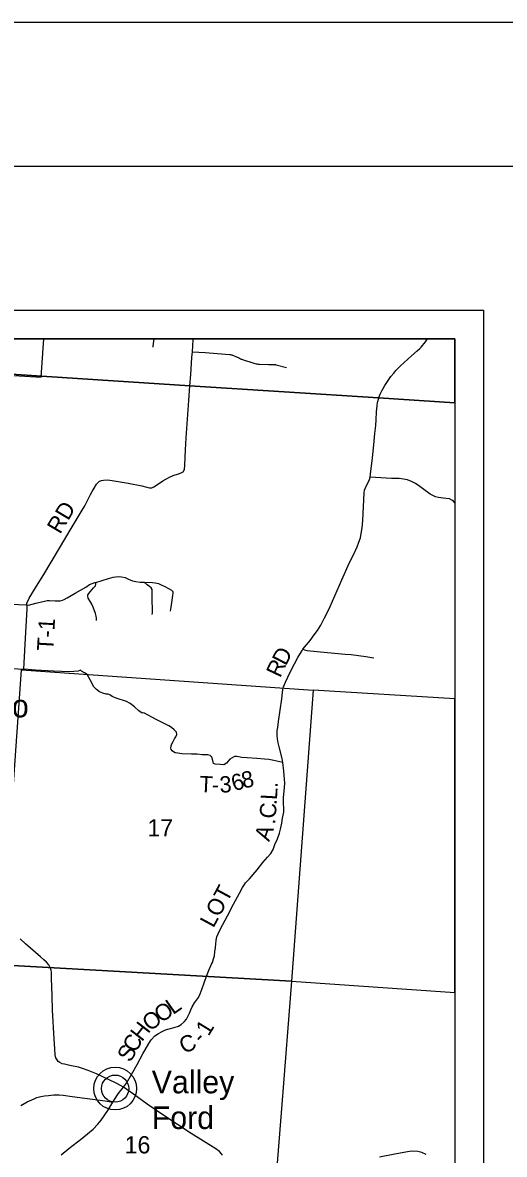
# Model space of a CAD drawing. Extents: x 0 to 34, y 0 to 22.
# Drawn here: x 7.394 to 9.072, y 18.062 to 22 of the extents above; entities that cross this region are included whole.
import ezdxf

# ---------------------------------------------------------------- set-up
doc = ezdxf.new("R2010")
doc.units = 0
for name, color, linetype in [('GM_X_Corporation', 7, 'Continuous'), ('GM_X_County_Road', 7, 'Continuous'), ('GM_X_County_Road_Text', 7, 'Continuous'), ('GM_X_Section_Text', 7, 'Continuous'), ('GM_X_State_Route', 7, 'Continuous'), ('GM_X_Township_Road', 7, 'Continuous'), ('GM_X_Township_Road_Text', 7, 'Continuous'), ('GM_X_Township_Text', 7, 'Continuous'), ('GM_X_Unincorporated', 7, 'Continuous'), ('GM_X_Unincorporated_Location', 7, 'Continuous'), ('GM_X_Unincorporated_Text', 7, 'Continuous'), ('SH_Border', 7, 'Continuous'), ('SH_Cut_Line', 7, 'Continuous'), ('SH_Data', 7, 'Continuous')]:
    doc.layers.add(name, color=color, linetype=linetype)

msp = doc.modelspace()

# ---------------------------------------------------------------- linework, layer by layer
at = {"layer": 'GM_X_Corporation'}
for points in [[(8.9, 20.6767), (8.9, 20.9), (6.4339, 20.9), (6.4275, 20.8307), (6.8677, 20.8085), (6.8847, 20.8074), (7.2108, 20.7862), (7.9767, 20.7364), (8.6343, 20.694)], [(8.9, 20.6767), (8.9, 20.9), (6.4339, 20.9), (6.4275, 20.8307), (6.8677, 20.8085), (6.8847, 20.8074), (7.2108, 20.7862), (7.9767, 20.7364), (8.6343, 20.694)], [(7.4684, 20.9), (6.4334, 20.9), (6.4281, 20.8286), (7.4587, 20.7663)], [(7.3904, 19.7475), (8.4063, 19.6773), (8.3303, 18.6644), (7.3179, 18.7214)], [(8.9, 18.6256), (8.9, 19.6469), (8.4063, 19.6773), (8.3303, 18.6644)], [(7.3179, 18.7214), (8.3303, 18.6644), (8.2967, 18.2357), (8.2648, 17.8281), (8.2474, 17.6405), (7.6907, 17.673), (7.2488, 17.7032), (7.2611, 17.894), (7.2923, 18.3534)]]:
    msp.add_lwpolyline(points, close=True, dxfattribs=at)
at = {"layer": 'GM_X_County_Road'}
for points in [[(8.6345, 20.6935), (8.6374, 20.7012), (8.64, 20.707), (8.6453, 20.7182), (8.6496, 20.7264), (8.6557, 20.7372), (8.6623, 20.7477), (8.6696, 20.7584), (8.677, 20.7684), (8.6867, 20.7805), (8.6943, 20.7894), (8.6969, 20.7924), (8.6998, 20.7953), (8.71, 20.8053), (8.7483, 20.8406), (8.7685, 20.8581), (8.7776, 20.8665), (8.7819, 20.8709), (8.787, 20.8764), (8.793, 20.8836), (8.7976, 20.8895), (8.8049, 20.9)], [(7.746, 18.2957), (7.756, 18.3098), (7.7736, 18.3395), (7.7936, 18.3746), (7.8133, 18.4121), (7.8333, 18.4476), (7.8417, 18.4609), (7.855, 18.4742), (7.867, 18.4828), (7.8798, 18.4898), (7.8922, 18.4947), (7.9052, 18.499), (7.922, 18.5034), (7.9367, 18.508), (7.9461, 18.5134), (7.957, 18.5227), (7.965, 18.5326), (7.9699, 18.5412), (7.9757, 18.5531), (7.9801, 18.5648), (7.9851, 18.5755), (7.9928, 18.5893), (8.0072, 18.608), (8.0131, 18.6201), (8.0196, 18.6393), (8.0254, 18.6549), (8.0341, 18.6824), (8.0436, 18.7053), (8.0525, 18.7235), (8.0551, 18.7301), (8.0595, 18.7424), (8.0623, 18.7527), (8.0642, 18.7667), (8.0663, 18.7823), (8.0674, 18.7937), (8.0686, 18.8069), (8.0709, 18.819), (8.0752, 18.8295), (8.0835, 18.8463), (8.1074, 18.892), (8.1288, 18.9324), (8.1494, 18.9705), (8.1601, 18.9906), (8.1643, 18.9973), (8.1666, 19.0008), (8.1706, 19.0064), (8.1839, 19.0209), (8.2112, 19.0524), (8.2313, 19.0778), (8.2476, 19.096), (8.2582, 19.1086), (8.2663, 19.1229), (8.2729, 19.1402), (8.2824, 19.1603), (8.2892, 19.1794), (8.2927, 19.1932), (8.2965, 19.2144), (8.2993, 19.2321), (8.3035, 19.2524), (8.3035, 19.2669), (8.3027, 19.2828), (8.303, 19.3036), (8.3065, 19.3369), (8.3074, 19.3549), (8.3067, 19.3664), (8.3035, 19.3956), (8.3003, 19.4249), (8.2978, 19.4397), (8.2881, 19.4797), (8.2846, 19.4934), (8.2823, 19.5078), (8.281, 19.52), (8.2803, 19.5271), (8.281, 19.5369), (8.2827, 19.547), (8.2858, 19.5686), (8.2969, 19.6475), (8.2992, 19.6693), (8.3009, 19.6794), (8.303, 19.6892), (8.3095, 19.7049), (8.3174, 19.7223), (8.3296, 19.7466), (8.3524, 19.7914), (8.3673, 19.8155), (8.3706, 19.8198), (8.3828, 19.8354), (8.3956, 19.8503), (8.4098, 19.8693), (8.4207, 19.8844), (8.4333, 19.9031), (8.4461, 19.9286), (8.4549, 19.9462), (8.4653, 19.9688), (8.5066, 20.0606), (8.5324, 20.1211), (8.5466, 20.1482), (8.5598, 20.1756), (8.5652, 20.1921), (8.5705, 20.2068), (8.5738, 20.2225), (8.5772, 20.242), (8.5789, 20.2678), (8.5839, 20.3639), (8.5855, 20.3734), (8.5914, 20.389), (8.599, 20.4022), (8.6027, 20.4108), (8.605, 20.4188), (8.6076, 20.4395), (8.6134, 20.4848), (8.6189, 20.5438), (8.6212, 20.5706), (8.6241, 20.5977), (8.6257, 20.6176), (8.6266, 20.6458), (8.6289, 20.6668), (8.6306, 20.6783), (8.6345, 20.6935)], [(7.528, 18.0608), (7.5551, 18.0823), (7.6001, 18.1169), (7.6277, 18.1395), (7.64, 18.1491), (7.6564, 18.1666), (7.6681, 18.1806), (7.691, 18.2151), (7.7089, 18.2433), (7.725, 18.2692), (7.7305, 18.2776), (7.7363, 18.2845), (7.746, 18.2957)]]:
    msp.add_lwpolyline(points, dxfattribs=at)
at = {"layer": 'GM_X_State_Route'}
for points in [[(8.0901, 18.0591), (8.087, 18.0635), (8.0798, 18.0713), (8.0667, 18.081), (7.9816, 18.1341), (7.9335, 18.1654), (7.8716, 18.2066), (7.8284, 18.2364), (7.7805, 18.2714), (7.746, 18.2957), (7.7224, 18.3084), (7.6914, 18.3239), (7.652, 18.3422), (7.6224, 18.3543), (7.6029, 18.3612), (7.5884, 18.3649), (7.5584, 18.3716), (7.5405, 18.3753), (7.5323, 18.3775), (7.5237, 18.3812), (7.5182, 18.3855), (7.5143, 18.3904), (7.5101, 18.3983), (7.5078, 18.4087), (7.5066, 18.4295), (7.5044, 18.4634), (7.4989, 18.5639), (7.4968, 18.6133), (7.4948, 18.6747), (7.4944, 18.6957), (7.4931, 18.7028), (7.4903, 18.7122), (7.4852, 18.7214), (7.4772, 18.7304), (7.4679, 18.7391), (7.4566, 18.7487), (7.4389, 18.7644), (7.4042, 18.795), (7.3853, 18.8123)], [(8.7998, 18.061), (8.7847, 18.0685), (8.7706, 18.0716), (8.7537, 18.0725), (8.7415, 18.0714), (8.6961, 18.0633), (8.6367, 18.0516)]]:
    msp.add_lwpolyline(points, dxfattribs=at)
at = {"layer": 'GM_X_Township_Road'}
for points in [[(7.8488, 20.8709), (7.8493, 20.8744), (7.8517, 20.8914), (7.8524, 20.9)], [(7.9769, 20.7358), (7.9796, 20.7761), (7.9838, 20.8352), (7.9856, 20.8547), (7.9885, 20.8964), (7.9887, 20.9)], [(7.9856, 20.8547), (8.0303, 20.8519), (8.0729, 20.8484), (8.1145, 20.8452), (8.1171, 20.8449), (8.1201, 20.8445), (8.1228, 20.844), (8.1255, 20.8432), (8.1284, 20.8423), (8.1316, 20.841), (8.1364, 20.8388), (8.1495, 20.832), (8.1528, 20.8305), (8.1553, 20.8295), (8.158, 20.8284), (8.1662, 20.8255), (8.1853, 20.8192), (8.203, 20.8141), (8.2079, 20.8131), (8.2105, 20.8126), (8.2133, 20.8121), (8.2162, 20.8117), (8.219, 20.8114), (8.2501, 20.8106), (8.2731, 20.8101), (8.2746, 20.8099), (8.2761, 20.8096), (8.2776, 20.8092), (8.3135, 20.8005)], [(7.408, 19.9745), (7.4097, 19.9827), (7.4174, 19.9974), (7.4393, 20.0338), (7.454, 20.0575), (7.4683, 20.0794), (7.5229, 20.171), (7.5638, 20.2398), (7.6016, 20.303), (7.611, 20.3189), (7.6184, 20.3326), (7.6308, 20.3582), (7.6364, 20.369), (7.6435, 20.3799), (7.6519, 20.3936), (7.6572, 20.4003), (7.6625, 20.4042), (7.6693, 20.4068), (7.676, 20.4083), (7.6893, 20.4085), (7.7057, 20.4068), (7.7617, 20.397), (7.8099, 20.3878), (7.8269, 20.3835), (7.8363, 20.3817), (7.8442, 20.3815), (7.8514, 20.3842), (7.8635, 20.3923), (7.8831, 20.406), (7.8927, 20.4115), (7.9054, 20.4185), (7.9191, 20.424), (7.9366, 20.4299), (7.9469, 20.433), (7.9536, 20.4371), (7.9577, 20.4453), (7.9595, 20.4604), (7.9612, 20.5137), (7.9634, 20.5548), (7.9727, 20.6846), (7.9769, 20.7358)], [(8.9, 20.3295), (8.8949, 20.3353), (8.8891, 20.3385), (8.8805, 20.3425), (8.8594, 20.3454), (8.8432, 20.3474), (8.8328, 20.3501), (8.825, 20.3531), (8.8142, 20.3594), (8.7921, 20.3753), (8.778, 20.3861), (8.7625, 20.3965), (8.749, 20.4034), (8.735, 20.4088), (8.7213, 20.4118), (8.7062, 20.4136), (8.6786, 20.414), (8.605, 20.4188)], [(7.408, 19.9745), (7.4151, 19.9734), (7.4406, 19.9796), (7.47, 19.9867), (7.4795, 19.9891), (7.4882, 19.9897), (7.5079, 19.9883), (7.5182, 19.9881), (7.5255, 19.9885), (7.5328, 19.9902), (7.5388, 19.993), (7.549, 19.9982), (7.5768, 20.0143), (7.614, 20.0358), (7.6277, 20.0446), (7.6366, 20.0485), (7.646, 20.0514)], [(7.6516, 19.9191), (7.6516, 19.9282), (7.6502, 19.9351), (7.6478, 19.944), (7.6401, 19.9655), (7.635, 19.9762), (7.6279, 19.9885), (7.6227, 19.9978), (7.6212, 20.0043), (7.6219, 20.0092), (7.6299, 20.0194), (7.6417, 20.0327), (7.6476, 20.0404), (7.649, 20.0456), (7.6488, 20.0523)], [(7.646, 20.0514), (7.6488, 20.0523), (7.6929, 20.0661), (7.7091, 20.0701), (7.7188, 20.072), (7.7294, 20.0726), (7.7389, 20.0719), (7.7509, 20.0689), (7.7628, 20.0638), (7.7771, 20.058), (7.7885, 20.0553), (7.8039, 20.0535), (7.8166, 20.0533)], [(7.8166, 20.0533), (7.8176, 20.0533), (7.8463, 20.0513), (7.8563, 20.0504), (7.868, 20.0478), (7.8771, 20.0442), (7.8867, 20.0394), (7.9049, 20.03), (7.9126, 20.0254), (7.917, 20.0209), (7.9174, 20.0161), (7.9168, 20.0061), (7.911, 19.9663), (7.9087, 19.9523)], [(7.8456, 19.9399), (7.8462, 19.9464), (7.8462, 19.9523), (7.8462, 19.965), (7.8454, 19.9829), (7.846, 20.0197), (7.8452, 20.028), (7.8423, 20.0331), (7.8367, 20.0381), (7.8284, 20.0436), (7.8176, 20.0533)], [(6.7345, 19.7916), (6.8105, 19.7864), (6.91, 19.7796), (7.0256, 19.7732), (7.1508, 19.7653), (7.198, 19.7624), (7.2941, 19.7563), (7.3981, 19.7503), (7.4029, 19.8375), (7.41, 19.9599), (7.41, 19.9692), (7.408, 19.9745)], [(6.8078, 19.987), (6.8835, 19.9849), (6.955, 19.9837), (7.0769, 19.9809), (7.1529, 19.9784), (7.2703, 19.9768), (7.3804, 19.9749), (7.408, 19.9745)], [(8.3706, 19.8198), (8.3759, 19.817), (8.3836, 19.8153), (8.4559, 19.8079), (8.5171, 19.8029), (8.5386, 19.8011), (8.5895, 19.7944), (8.6172, 19.7893)], [(7.6293, 19.7131), (7.6192, 19.7313), (7.6096, 19.737), (7.599, 19.7435), (7.5953, 19.7463), (7.5931, 19.7461), (7.5881, 19.7437), (7.5575, 19.7405), (7.5019, 19.7437), (7.4391, 19.7469), (7.3981, 19.7503)], [(8.0645, 19.4191), (8.0586, 19.422), (8.0573, 19.432), (8.0533, 19.4446), (8.048, 19.4498), (8.0395, 19.452), (8.0201, 19.4523), (8.0017, 19.4545), (7.9821, 19.455), (7.9489, 19.4558), (7.9347, 19.4578), (7.926, 19.4595), (7.9196, 19.463), (7.9147, 19.4658), (7.9114, 19.4704), (7.91, 19.4748), (7.9114, 19.4833), (7.9141, 19.4899), (7.9187, 19.4981), (7.9234, 19.5073), (7.9283, 19.5153), (7.931, 19.5231), (7.9306, 19.5305), (7.9215, 19.5397), (7.9126, 19.5471), (7.9036, 19.5526), (7.8594, 19.5751), (7.8169, 19.5983), (7.8107, 19.5977), (7.7993, 19.6054), (7.7836, 19.619), (7.7689, 19.6304), (7.7564, 19.6375), (7.7203, 19.6492), (7.7065, 19.6547), (7.6983, 19.6612), (7.6927, 19.6627), (7.6856, 19.6632), (7.6731, 19.6669), (7.662, 19.6719), (7.6518, 19.6796), (7.6428, 19.6888), (7.6293, 19.7131)], [(8.3003, 19.4249), (8.2692, 19.4323), (8.2523, 19.4357), (8.2367, 19.437), (8.2095, 19.4389), (8.176, 19.4415), (8.1574, 19.4432), (8.1404, 19.4466), (8.1317, 19.4458), (8.1238, 19.4415), (8.1161, 19.4366), (8.1041, 19.4231), (8.0955, 19.4172), (8.0828, 19.4185), (8.0645, 19.4191)], [(7.3881, 18.2323), (7.4099, 18.2445), (7.434, 18.2557), (7.4438, 18.2596), (7.4576, 18.2633), (7.4701, 18.2651), (7.4844, 18.2672), (7.5035, 18.2686), (7.5219, 18.269), (7.5356, 18.2674), (7.5674, 18.2631), (7.6822, 18.248), (7.7089, 18.2433)]]:
    msp.add_lwpolyline(points, dxfattribs=at)
at = {"layer": 'GM_X_Township_Text'}
msp.add_lwpolyline([(8.9, 20.6767), (8.6343, 20.694), (7.9767, 20.7364), (7.2108, 20.7862), (6.8847, 20.8074), (6.8677, 20.8085), (6.4275, 20.8307), (5.5376, 20.8903), (5.3907, 20.9)], dxfattribs=at)
at = {"layer": 'GM_X_Unincorporated'}
for radius in [0.0744, 0.0472]:
    msp.add_circle((7.7165, 18.2907), radius, dxfattribs=at)
at = {"layer": 'GM_X_Unincorporated_Location'}
msp.add_line((7.7165, 18.2907), (7.7165, 18.2907), dxfattribs=at)
at = {"layer": 'SH_Border'}
msp.add_lwpolyline([(1.5, 21.5), (33.5, 21.5), (33.5, 0.5), (1.5, 0.5)], close=True, dxfattribs=at)
at = {"layer": 'SH_Cut_Line'}
msp.add_lwpolyline([(0, 0), (34, 0), (34, 22), (0, 22)], close=True, dxfattribs=at)
at = {"layer": 'SH_Data'}
for p, q in [((2, 21), (9, 21)), ((9, 21), (9, 14)), ((2.1, 20.9), (8.9, 20.9)), ((8.9, 20.9), (8.9, 14.1))]:
    msp.add_line(p, q, dxfattribs=at)

# ---------------------------------------------------------------- texts
at = {"layer": 'GM_X_County_Road_Text'}
for s, height, rotation, p in [('D', 0.0568, 62.7654, (8.3108, 19.7594)), ('R', 0.0568, 64.7931, (8.2912, 19.7176)), ('.', 0.0568, 86.8554, (8.2823, 19.3366)), ('L', 0.0568, 86.8678, (8.28, 19.2942)), ('C', 0.0568, 85.9364, (8.2756, 19.2291)), ('.', 0.0568, 86.8472, (8.279, 19.2767)), ('.', 0.0568, 83.2424, (8.2733, 19.2088)), ('A', 0.0568, 69.9083, (8.2528, 19.1479)), ('LOT', 0.05682, 61.706, (8.0587, 18.8472)), ('L', 0.0568, 35.0928, (7.9182, 18.5462)), ('O', 0.0568, 36.1843, (7.8372, 18.4881)), ('O', 0.0568, 35.1057, (7.8773, 18.5175)), ('H', 0.0568, 52.3199, (7.8097, 18.4515)), ('1', 0.0568, 58.4517, (8.0418, 18.4708)), ('C', 0.0568, 61.1425, (7.7884, 18.4126)), ('C', 0.0568, 24.0089, (7.9554, 18.4107)), ('-', 0.0568, 46.4296, (8.0177, 18.4436)), ('S', 0.0568, 61.2925, (7.77, 18.379))]:
    msp.add_text(s, height=height, rotation=rotation, dxfattribs=at).set_placement(p)
at = {"layer": 'GM_X_Section_Text'}
for s, p in [('17', (7.8289, 19.1682)), ('16', (7.7498, 18.0652))]:
    msp.add_text(s, height=0.06, rotation=0, dxfattribs=at).set_placement(p)
at = {"layer": 'GM_X_Township_Road_Text'}
for s, height, rotation, p in [('RD', 0.05682, 59.2073, (7.5247, 20.2174)), ('T-1', 0.05682, 86.6532, (7.5008, 19.8126)), ('T', 0.0568, 357.2134, (8.0089, 19.3225)), ('3', 0.0568, 3.5777, (8.0816, 19.3199)), ('6', 0.0568, 17.072, (8.1309, 19.3247)), ('8', 0.0568, 12.5316, (8.1632, 19.3346)), ('-', 0.0568, 358.5459, (8.0528, 19.3204))]:
    msp.add_text(s, height=height, rotation=rotation, dxfattribs=at).set_placement(p)
at = {"layer": 'GM_X_Unincorporated_Text'}
for s, height, p in [('Mount Blanco', 0.078977, (6.7698, 19.5826)), ('Valley', 0.07898, (7.8439, 18.2743)), ('Ford', 0.07898, (7.8439, 18.1501))]:
    msp.add_text(s, height=height, rotation=0, dxfattribs=at).set_placement(p)

doc.saveas('drawing.dxf')
